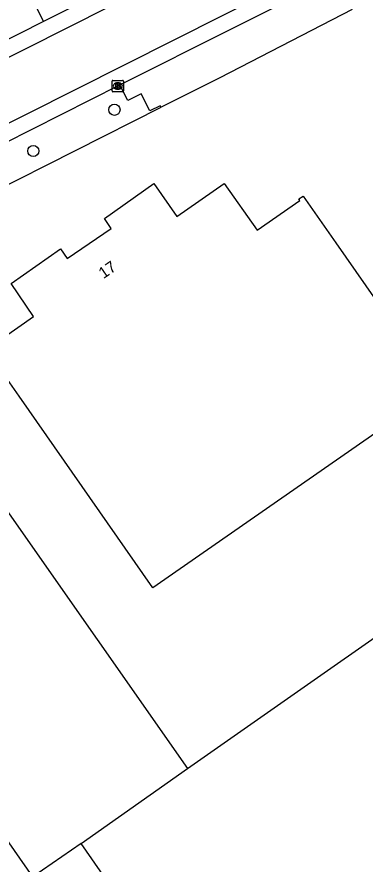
# Model space of a CAD drawing. Extents: x 156651 to 158072, y 387631 to 388990.
# Drawn here: x 157209.7 to 157240.2, y 388268.5 to 388342.7 of the extents above; entities that cross this region are included whole.
import ezdxf

# ---------------------------------------------------------------- set-up
doc = ezdxf.new("R2010")
doc.units = 0
for name, color, linetype in [('IMGEO_Berm_groen', 7, 'Continuous'), ('IMGEO_Boom', 7, 'Continuous'), ('IMGEO_Kolk', 7, 'Continuous'), ('IMGEO_Pand', 7, 'Continuous'), ('IMGEO_Pand_nummerreeks', 7, 'Continuous'), ('IMGEO_Parkeervlak_gesloten', 7, 'Continuous'), ('IMGEO_Rijbaan_lokaal_gesloten', 7, 'Continuous'), ('IMGEO_Rijbaan_lokaal_open', 7, 'Continuous'), ('IMGEO_Voetpad_open', 7, 'Continuous')]:
    doc.layers.add(name, color=color, linetype=linetype)

msp = doc.modelspace()

# ---------------------------------------------------------------- linework, layer by layer
at = {"layer": 'IMGEO_Berm_groen'}
msp.add_lwpolyline([(157199.814, 388323.396), (157222.36, 388334.779)], dxfattribs=at)
at = {"layer": 'IMGEO_Boom'}
for centre in [(157218.263, 388334.554), (157211.148, 388330.946)]:
    msp.add_circle(centre, 0.489, dxfattribs=at)
at = {"layer": 'IMGEO_Kolk'}
for p, q in [((157218.053, 388336.205), (157218.053, 388337.057)), ((157218.128, 388337.131), (157218.98, 388337.131)), ((157218.541, 388336.911), (157218.566, 388336.911)), ((157219.054, 388337.057), (157219.054, 388336.205)), ((157218.98, 388336.131), (157218.128, 388336.131)), ((157218.564, 388336.351), (157218.539, 388336.351))]:
    msp.add_line(p, q, dxfattribs=at)
for points in [[(157218.053, 388336.205), (157218.053, 388337.057)], [(157218.128, 388337.131), (157218.98, 388337.131)], [(157218.374, 388336.831), (157218.497, 388336.831), (157218.497, 388336.68), (157218.627, 388336.831), (157218.791, 388336.831), (157218.645, 388336.68), (157218.798, 388336.431), (157218.646, 388336.431), (157218.561, 388336.595), (157218.497, 388336.528), (157218.497, 388336.431), (157218.374, 388336.431), (157218.374, 388336.831)], [(157219.054, 388337.057), (157219.054, 388336.205)], [(157218.98, 388336.131), (157218.128, 388336.131)]]:
    msp.add_lwpolyline(points, dxfattribs=at)
for centre, start, end in [((157218.13, 388337.055), 91.55205, 178.44795), ((157218.13, 388337.055), 91.55205, 178.44795), ((157218.978, 388337.055), 1.55205, 88.44795), ((157218.978, 388337.055), 1.55205, 88.44795), ((157218.13, 388336.207), 181.55205, 268.44795), ((157218.13, 388336.207), 181.55205, 268.44795), ((157218.978, 388336.207), 271.55205, 358.44795), ((157218.978, 388336.207), 271.55205, 358.44795)]:
    msp.add_arc(centre, 0.0765, start, end, dxfattribs=at)
for centre, major_axis, ratio, start_param, end_param in [((157218.54, 388336.631), (-0.387, 0.002), 0.722429, 4.712389, 7.853982), ((157218.565, 388336.631), (-0.39, 0.002), 0.717154, 1.570796, 4.712389)]:
    msp.add_ellipse(centre, major_axis=major_axis, ratio=ratio, start_param=start_param, end_param=end_param, dxfattribs=at)
at = {"layer": 'IMGEO_Pand'}
for points in [[(157221.636, 388292.685), (157209.901, 388309.471), (157207.036, 388313.568), (157211.174, 388316.441), (157209.2, 388319.351), (157213.545, 388322.37), (157214.133, 388321.521), (157217.975, 388324.161), (157217.382, 388325.047), (157221.715, 388328.093), (157223.723, 388325.208), (157227.881, 388328.096), (157230.772, 388324.002), (157234.509, 388326.621), (157234.43, 388326.764), (157234.793, 388326.999), (157237.656, 388322.9), (157246.632, 388310.052), (157221.636, 388292.685)], [(157208.838, 388299.477), (157224.658, 388276.883)], [(157224.658, 388276.883), (157252.506, 388296.33), (157266.462, 388276.354), (157235.802, 388254.933), (157231.703, 388252.069), (157226.167, 388259.993), (157223.715, 388258.28), (157221.495, 388261.458), (157221.333, 388261.345), (157220.992, 388261.833), (157222.145, 388262.639), (157220.935, 388264.371), (157219.786, 388263.574), (157219.437, 388264.047), (157219.61, 388264.167), (157215.353, 388270.292)], [(157215.353, 388270.292), (157211.106, 388267.393), (157202.392, 388279.88), (157198.304, 388277.05), (157196.864, 388279.117), (157194.804, 388277.677), (157189.199, 388285.691)], [(157215.353, 388270.292), (157224.658, 388276.883)]]:
    msp.add_lwpolyline(points, dxfattribs=at)
at = {"layer": 'IMGEO_Parkeervlak_gesloten'}
msp.add_lwpolyline([(157200.913, 388327.752), (157218.736, 388336.736)], dxfattribs=at)
at = {"layer": 'IMGEO_Rijbaan_lokaal_gesloten'}
for points in [[(157427.649, 388413.564), (157313.182, 388386.746), (157307.564, 388385.322), (157304.11, 388384.347), (157298.594, 388382.628), (157295.094, 388381.431), (157289.829, 388379.374), (157285.802, 388377.632), (157280.387, 388375.114), (157169.957, 388319.498), (157169.378, 388320.773)], [(157171.244, 388314.319), (157180.605, 388319.095), (157279.127, 388368.703), (157285.498, 388371.81), (157294.645, 388375.709), (157303.766, 388378.867), (157314.242, 388381.65), (157428.83, 388408.527)], [(157245.122, 388358.93), (157212.051, 388342.27)], [(157212.051, 388342.27), (157201.348, 388336.878)]]:
    msp.add_lwpolyline(points, dxfattribs=at)
at = {"layer": 'IMGEO_Rijbaan_lokaal_open'}
for points in [[(157218.736, 388336.736), (157238.524, 388346.687)], [(157239.077, 388343.333), (157227.498, 388337.345), (157222.36, 388334.779)], [(157222.36, 388334.779), (157222.274, 388334.914), (157221.376, 388334.463), (157220.601, 388335.944), (157219.436, 388335.357), (157218.736, 388336.736)]]:
    msp.add_lwpolyline(points, dxfattribs=at)
at = {"layer": 'IMGEO_Voetpad_open'}
msp.add_lwpolyline([(157210.905, 388344.546), (157212.051, 388342.27)], dxfattribs=at)

# ---------------------------------------------------------------- texts
at = {"layer": 'IMGEO_Pand_nummerreeks'}
msp.add_text('17', height=1, rotation=34.4946, dxfattribs=at).set_placement((157217.305, 388319.721))

doc.saveas('drawing.dxf')
